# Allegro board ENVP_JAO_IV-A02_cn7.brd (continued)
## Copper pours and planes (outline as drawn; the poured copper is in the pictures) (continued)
VDD_1V2 on L4-VCC1: 129.01,41.27 135.66,41.27 136.47,40.46 136.55,40.41 136.65,40.39 146.2,40.39 147.07,39.52 147.07,32.11 146.71,31.75 145.54,31.75 145.44,31.73 145.36,31.68 145.18,31.5 137.41,31.5 137.32,31.48 137.23,31.42 136.47,30.66 136.42,30.58 136.4,30.48 136.4,27.03 136.04,26.67 128.12,26.67 127.76,27.03 127.76,40.03
VDD_1V8 on TOP: 87.63,77.22 87.88,77.47 90.17,77.47 90.42,77.22 90.42,73.09 90.17,72.83 87.82,72.83 87.63,73.03
VDD_1V8 on TOP: 42.93,71.37 41.91,71.37 41.66,71.12 41.66,69.09 41.78,68.96 43.43,68.96 43.56,69.09 43.56,69.72 43.18,70.1 43.18,71.12
VDD_1V8 on L3-IN1: 35.94,86.49 35.94,69.22 36.2,68.96 43.56,68.96 43.81,69.22 43.81,86.36 43.31,86.87 36.32,86.87
VDD_1V8 on L5-VCC2: outline of 230 points within 12.7,16 186.31,102.87 ; 4 cut-outs
VDD_1V8 on L6-IN2: 35.81,86.87 41.66,86.87 42.67,85.85 42.67,77.47 42.42,77.22 37.34,77.22 35.56,78.99 35.56,86.61
VDD_1V8_DISCHARGE on TOP: 90.93,73.15 92.96,73.15 93.22,73.41 93.22,78.49 92.96,78.74 90.93,78.74 90.68,78.49 90.68,73.41
VDD_3V3 on TOP: 15.24,66.17 13.59,66.17 13.46,66.04 13.46,62.87 14.1,62.87 14.1,63.37 14.22,63.5 15.24,63.5 15.37,63.63 15.37,66.04
VDD_3V3 on BOTTOM: 38.48,93.73 40.89,93.73 41.15,93.47 41.15,87.88 40.89,87.63 35.69,87.63 35.43,87.88 35.43,89.66 35.69,89.92 37.85,89.92 38.23,90.3 38.23,93.47
VDD_3V3 on L4-VCC1: outline of 148 points within 72.39,30.23 182.37,138.43
VDD_3V3 on L5-VCC2: outline of 105 points within 35.43,70.36 166.37,114.05
VDD_3V3 on L5-VCC2: 47.22,38.73 54.63,38.73 54.81,38.56 54.89,38.5 54.99,38.48 60.73,38.48 64.84,34.36 64.93,34.31 65.02,34.29 76.6,34.29 76.96,33.93 76.96,32.51 76.98,32.41 77.04,32.33 77.72,31.64 77.72,30.46 77.49,30.23 67.18,30.23 67.09,30.21 67,30.15 66.44,29.59 46.46,29.59 45.97,30.08 45.97,37.49
VDD_3V3_DISCHARGE on BOTTOM (solid shape): 44.45,90.42 44.45,87.88 44.2,87.63 41.91,87.63 41.66,87.88 41.66,91.19 41.91,91.44 43.43,91.44
VDD_3V3_PD on TOP (solid shape): 49.02,108.2 50.04,108.2 50.29,107.95 50.29,102.87 50.04,102.62 48.01,102.62 47.75,102.87 47.75,107.82 47.62,107.95 47.62,108.33 48.9,108.33
VDD_3V3_PD on BOTTOM (solid shape): 49.53,107.95 49.53,102.87 49.28,102.62 48.01,102.62 47.75,102.87 47.75,107.95 48.01,108.2 49.28,108.2
VDD_3V3_PD on BOTTOM: 49.78,89.41 58.42,89.41 61.47,86.36 61.47,71.88 58.42,68.83 50.04,68.83 49.53,69.34 49.53,71.12 49.78,71.37 53.59,71.37 53.85,71.63 53.85,72.64 54.1,72.9 55.75,72.9 58.17,75.31 58.17,78.23 58.93,78.99 58.93,86.61 57.91,87.63 53.85,87.63 53.09,88.39 49.78,88.39 49.53,88.65 49.53,89.15
VDD_3V3_PD on L3-IN1: 46.48,77.47 46.48,72.64 48.01,71.12 53.09,71.12 53.34,70.87 53.34,69.34 53.09,69.09 44.45,69.09 44.2,69.34 44.2,78.74 44.45,78.99 44.96,78.99
VDD_3V3_PD on L4-VCC1: 44.81,111 60.35,111 65.28,106.07 65.28,82.15 64.92,81.79 63.75,81.79 63.66,81.77 63.57,81.71 61.36,79.5 59.29,79.5 57.84,80.95 57.76,81.01 57.66,81.03 48.37,81.03 46.99,82.4 46.99,86 51.67,90.68 58.17,90.68 58.26,90.7 58.35,90.75 58.98,91.39 59.04,91.47 59.05,91.57 59.05,106.17 59.04,106.27 58.98,106.35 58.47,106.86 58.39,106.91 58.29,106.93 51.31,106.93 51.21,106.91 51.13,106.86 50.11,105.84 50.06,105.76 50.04,105.66 50.04,103.48 49.42,102.87 43.79,102.87 43.43,103.23 43.43,106.98 44.3,107.84 44.41,108.01 44.45,108.2 44.45,110.64
VDD_3V3_PD on L6-IN2: 40.64,108.2 49.53,108.2 49.78,107.95 49.78,92.46 52.32,89.92 56.39,89.92 61.34,84.96 61.34,79.88 61.21,79.76 53.59,79.76 51.31,82.04 50.29,82.04 50.04,81.79 47.5,81.79 40.39,88.9 40.39,107.95
VDD_5V on TOP (solid shape): 52.07,64.52 52.07,57.91 51.82,57.66 41.91,57.66 41.66,57.91 41.66,59.69 41.4,59.94 41.4,64.52 41.66,64.77 51.82,64.77
VDD_5V on TOP (solid shape): 89.41,58.17 89.41,56.13 88.65,55.37 88.65,54.61 87.25,53.21 87.25,51.82 87.12,51.69 87,51.69 86.87,51.82 86.87,52.32 86.74,52.45 86.36,52.45 86.23,52.58 86.23,53.47 85.85,53.85 85.85,58.17 86.11,58.42 89.15,58.42
VDD_5V on BOTTOM (solid shape): 52.07,64.52 52.07,57.91 51.82,57.66 41.66,57.66 41.4,57.91 41.4,64.52 41.66,64.77 51.82,64.77
VDD_5V on TOP: 34.29,66.17 34.42,66.04 36.07,66.04 36.53,66.5 40.46,66.5 40.89,66.93 40.89,68.33 40.77,68.45 36.07,68.45 35.94,68.33 35.94,67.69 35.69,67.44 34.54,67.44 34.29,67.18
VDD_5V on TOP: 85.09,105.66 85.85,106.43 86.36,106.43 86.49,106.55 86.49,107.57 86.61,107.7 86.87,107.7 86.87,106.68 87.5,106.05 87.5,100.2 87.38,100.08 83.82,100.08 83.69,100.2 83.69,103.12 83.82,103.25 84.84,103.25 85.09,103.5
VDD_5V on TOP: 31.62,84.84 31.62,82.3 31.75,82.17 33.15,82.17 34.8,80.52 34.8,77.09 35.18,76.71 39.62,76.71 39.88,76.96 39.88,84.84 39.5,85.22 32,85.22
VDD_5V on BOTTOM: 85.09,106.17 85.34,106.43 86.87,106.43 87.12,106.17 87.12,101.85 85.34,100.08 83.82,100.08 83.69,100.2 83.69,103.12 83.82,103.25 84.84,103.25 85.09,103.5
VDD_5V on BOTTOM: 86.11,58.42 85.85,58.17 85.85,52.58 86.11,52.32 89.03,52.32 89.28,52.58 89.28,58.23 89.09,58.42
VDD_5V on BOTTOM: 182.88,29.46 181.61,29.46 181.48,29.34 181.48,28.07 181.61,27.94 182.88,27.94 183.01,28.07 183.01,29.34
VDD_5V on L4-VCC1: outline of 397 points within 7.62,1.02 187.71,110.87 ; 1 cut-out
VDD_12V on TOP (solid shape): 84.71,135.51 84.71,132.97 84.58,132.84 80.52,132.84 80.39,132.97 80.39,135.51 80.52,135.64 84.58,135.64
VDD_12V on BOTTOM (solid shape): 84.71,135.51 84.71,132.97 84.58,132.84 81.53,132.84 81.28,133.1 81.28,135.38 81.53,135.64 84.58,135.64
VDD_12V on L5-VCC2: 76.45,138.07 76.84,138.46 181.5,138.43 181.61,138.32 181.61,124.57 181.25,124.21 166.73,124.21 164.26,126.67 164.18,126.73 164.08,126.75 85.45,126.75 84.51,127.69 84.43,127.74 84.33,127.76 76.81,127.76 76.45,128.12
VDD_12V_DISCHARGE on TOP (solid shape): 80.01,135.51 80.01,132.97 79.88,132.84 76.83,132.84 76.58,133.1 76.58,135.38 76.83,135.64 79.88,135.64
VDD_AV1V1_HUB on L4-VCC1: 78.59,48.01 92.86,48.01 93.22,47.65 93.22,41.76 89.3,37.85 79.76,37.85 78.99,38.61 77.85,38.61 77.6,38.35 77.6,37.97 78.23,37.34 78.23,36.94 76.09,34.8 74.02,34.8 73.66,35.16 73.66,36.07 73.64,36.17 73.59,36.25 73.08,36.76 73,36.81 72.9,36.83 67.69,36.83 67.59,36.81 67.51,36.76 67.26,36.5 67.2,36.42 67.18,36.32 67.18,35.81 67.2,35.72 67.26,35.63 67.69,35.2 67.69,35.03 67.59,34.92 66.53,34.92 64.26,37.19 64.26,39.01 67.24,41.98 67.29,42.07 67.31,42.16 67.31,43.07 69.19,44.96 73.53,44.96 73.63,44.98 73.71,45.03 75.04,46.35 76.83,46.35 76.93,46.37 77.01,46.43
VDDD_IN_CCG4 on TOP (solid shape): 44.45,108.97 44.45,108.58 44.7,108.33 45.47,108.33 45.47,107.95 45.21,107.7 45.21,101.35 44.96,101.09 41.66,101.09 41.4,101.35 41.4,108.97 41.66,109.22 44.2,109.22
VDDD_IN_CCG4 on BOTTOM: 41.4,102.87 41.4,107.19 41.66,107.44 44.2,107.44 44.45,107.19 44.45,102.87 44.2,102.62 41.66,102.62
CAM_2V8_SW on TOP: 85.09,110.49 84.58,111 84.58,111.76 84.84,112.01 85.6,112.01 85.85,111.76 85.85,111.51 86.11,111.25 88.14,111.25 88.39,111 88.39,108.97 88.14,108.71 87.63,108.71 87.5,108.58 87.5,107.31 87.38,107.19 87.25,107.19 87.12,107.31 87.12,108.97 86.61,109.47 85.34,109.47 85.09,109.73
DI_GND on TOP: 14.73,17.78 10.54,17.78 10.41,17.65 10.41,11.3 10.54,11.18 14.61,11.18 14.86,11.43 14.86,17.65
DI_GND on TOP: 12.06,22.48 9.4,22.48 9.27,22.35 9.27,21.21 9.4,21.08 10.03,21.08 10.41,20.7 10.41,19.94 10.54,19.81 12.06,19.81 12.19,19.94 12.19,22.35
DI_GND on L2-GND1, L4-VCC1, L5-VCC2, L7-GND2: 12.19,29.59 13.21,29.59 13.34,29.46 13.34,29.08 13.46,28.96 24.38,28.96 24.64,28.7 24.64,27.18 24.72,26.79 24.94,26.46 25.7,25.7 26.03,25.48 26.42,25.4 40.98,25.4 42.93,23.46 42.93,5.25 42.76,5.08 14.64,5.08 5.59,14.14 5.59,23.46 5.75,23.62 9.29,23.62 9.73,23.19 9.81,23.13 9.91,23.11 20.83,23.11 20.93,23.13 21.01,23.19 21.52,23.7 21.57,23.78 21.59,23.88 21.59,26.42 21.57,26.51 21.52,26.6 21.01,27.1 20.93,27.16 20.83,27.18 11.28,27.18 10.92,27.54 10.92,28.7 11.18,28.96 11.94,28.96 12.06,29.08 12.06,29.46
DO1_OUT on TOP: 10.92,19.3 10.92,18.41 11.05,18.29 12.95,18.29 13.08,18.41 13.08,19.3 12.95,19.43 11.05,19.43
DO1_OUT on BOTTOM: 12.62,23.04 10.34,23.04 10.24,22.94 10.24,18.44 10.39,18.29 13.13,18.29 13.21,18.36 13.21,20.12 12.59,20.74 12.59,21.4 12.67,21.49 12.67,22.99
DO2_OUT on TOP: 13.21,21.08 13.21,18.41 13.34,18.29 14.73,18.29 14.86,18.41 14.86,21.08 14.73,21.21 13.34,21.21
DO2_OUT on BOTTOM: 12.88,23.04 12.83,22.99 12.83,20.93 13.49,20.27 13.49,18.36 13.56,18.29 15.62,18.29 15.75,18.41 15.75,20.32 15.62,20.45 14.99,20.45 13.97,21.46 13.97,22.99 13.92,23.04
DO2_OUT on L3-IN1: 9.02,13.46 16.51,5.97 23.5,5.97 23.75,6.22 23.75,8.76 23.5,9.02 17.53,9.02 11.94,14.61 11.94,19.68 12.45,20.19 14.22,20.19 14.35,20.32 14.35,22.1 14.22,22.23 9.4,22.23 9.02,21.84
DO_GND1 on TOP: 12.06,46.48 12.06,45.72 12.19,45.59 13.46,45.59 13.59,45.72 13.59,46.48 13.46,46.61 12.19,46.61
DO_GND1 on BOTTOM: 12.19,45.59 13.46,45.59 13.59,45.72 13.59,46.48 13.46,46.61 12.19,46.61 12.06,46.48 12.06,45.72
DO_VIO on BOTTOM: 13.34,45.34 12.19,45.34 12.06,45.21 12.06,42.04 12.19,41.91 12.95,41.91 13.08,42.04 13.08,44.2 13.59,44.7 13.59,45.09
GB_AVDDL on L4-VCC1: 145.65,31.24 148.23,31.24 148.59,30.88 148.59,27.03 148.23,26.67 137.27,26.67 136.91,27.03 136.91,30.37 137.52,30.99 145.29,30.99 145.39,31.01 145.47,31.06
GB_VDDIO on L5-VCC2: 128.63,41.4 135.53,41.4 136.47,40.46 136.55,40.41 136.65,40.39 147.72,40.39 150.11,37.99 150.11,35.16 149.17,34.22 149.12,34.13 149.1,34.04 149.1,24.89 149.12,24.79 149.17,24.71 150.19,23.7 150.27,23.64 150.37,23.62 153.82,23.62 154.43,23.01 154.43,18.9 154.07,18.54 144.38,18.54 144.02,18.9 144.02,20.83 144,20.93 143.94,21.01 143.44,21.52 143.35,21.57 143.26,21.59 139.19,21.59 139.09,21.57 139.01,21.52 138.5,21.01 138.45,20.93 138.43,20.83 138.43,18.9 138.07,18.54 123.8,18.54 123.44,18.9 123.44,21.48 127.69,25.73 127.74,25.81 127.76,25.91 127.76,40.53
HDMI_GND on L2-GND1: outline of 92 points within 117.6,1.02 160.27,21.84
HDMI_GND on L2-GND1: outline of 113 points within 1.02,1.02 103.12,100.97
HDMI_GND on L4-VCC1: outline of 200 points within 1.02,1.02 160.27,100.97
HDMI_GND on L5-VCC2: outline of 206 points within 1.02,1.02 160.27,100.97
HDMI_GND on L7-GND2: outline of 197 points within 1.02,1.02 160.27,100.97
ISO1_5V on TOP: 8.89,11.18 10.03,11.18 10.16,11.3 10.16,14.73 10.03,14.86 8.51,14.86 8.38,14.73 8.38,12.83 8.76,12.45 8.76,11.3
M2B_3V3 on L5-VCC2: 158.6,82.04 165.5,82.04 165.86,81.68 165.86,73.66 165.88,73.56 165.94,73.48 166.37,73.05 166.37,57 166.01,56.64 158.6,56.64 158.24,57 158.24,81.68
M2E_3V3 on L5-VCC2: 145.9,78.49 148.23,78.49 148.59,78.13 148.59,75.44 148.61,75.34 148.66,75.26 150.11,73.81 150.11,59.03 149.75,58.67 146.28,58.67 145.8,59.16 145.8,69.34 145.78,69.44 145.72,69.52 144.53,70.72 144.53,75.59 145.09,76.15 145.14,76.23 145.16,76.33 145.16,77.75
M2M_3V3 on L5-VCC2: 157.59,105.92 162.58,105.92 162.81,105.69 162.81,103.18 162.81,103.12 162.81,102.41 162.81,102.35 162.81,91.95 162.83,91.85 162.89,91.77 163.32,91.33 163.32,87.48 161.95,86.11 158.32,86.11 157.73,86.7 157.73,98.04 157.71,98.14 157.66,98.22 157.23,98.66 157.23,105.56
M_USB_GND on L2-GND1, L4-VCC1: 182.78,138.98 188,138.98 188.69,138.7 188.98,138 188.98,114.04 189.36,114.04 189.36,113.16 188.98,113.16 188.98,105.03 189.36,105.03 189.36,104.14 188.98,104.14 188.98,87.36 188.49,86.87 187.3,86.87 186.82,87.35 186.82,101.98 186.8,102.08 186.74,102.16 185.6,103.3 185.52,103.36 185.42,103.38 182.48,103.38 182.12,103.74 182.12,104.54 182.73,105.16 183.79,105.16 184.22,104.72 184.31,104.67 184.4,104.65 185.42,104.65 185.52,104.67 185.6,104.72 186.11,105.23 186.16,105.31 186.18,105.41 186.18,113.28 186.16,113.38 186.11,113.46 185.47,114.1 185.39,114.15 185.29,114.17 184.53,114.17 184.43,114.15 184.35,114.1 183.28,113.03 182.48,113.03 182.12,113.39 182.12,117.24 182.48,117.6 186.44,117.6 186.53,117.62 186.62,117.68 187.12,118.18 187.18,118.27 187.2,118.36 187.2,127.76 187.18,127.86 187.12,127.94 182.12,132.95 182.12,138.32
M_USB_GND on L5-VCC2, L7-GND2: 182.78,138.98 188,138.98 188.69,138.7 188.98,138 188.98,114.04 189.36,114.04 189.36,113.16 188.98,113.16 188.98,105.03 189.36,105.03 189.36,104.14 188.98,104.14 188.98,87.36 188.49,86.87 187.3,86.87 186.82,87.35 186.82,101.98 186.8,102.08 186.74,102.16 185.6,103.3 185.52,103.36 185.42,103.38 182.48,103.38 182.12,103.74 182.12,104.54 182.73,105.16 183.79,105.16 184.22,104.72 184.31,104.67 184.4,104.65 185.42,104.65 185.52,104.67 185.6,104.72 186.11,105.23 186.16,105.31 186.18,105.41 186.18,113.03 186.16,113.13 186.11,113.21 185.85,113.46 185.77,113.52 185.67,113.54 184.91,113.54 184.81,113.52 184.73,113.46 184.3,113.03 182.48,113.03 182.12,113.39 182.12,117.24 182.48,117.6 186.44,117.6 186.53,117.62 186.62,117.68 187.12,118.18 187.18,118.27 187.2,118.36 187.2,127.76 187.18,127.86 187.12,127.94 182.12,132.95 182.12,138.32
MGBE_0V7 on L5-VCC2: 111.61,38.35 113.69,38.35 114.55,37.49 114.55,33.25 114.19,32.89 105.64,32.89 105.16,33.38 105.16,37.23 105.52,37.59 110.74,37.59 110.84,37.61 110.92,37.67
MGBE_VDDIO on L5-VCC2: 104.5,40.89 120.29,40.89 120.72,40.46 120.81,40.41 120.9,40.39 126.89,40.39 127.25,40.03 127.25,26.01 123.08,21.84 120.14,21.84 120.04,21.82 119.96,21.77 119.27,21.08 103.99,21.08 103.63,21.44 103.63,22.1 103.61,22.2 103.56,22.28 98.04,27.79 98.04,37.23 101.45,40.64 104.14,40.64 104.24,40.66 104.32,40.71 ; 1 cut-out
MIC2128_3V3_SW on TOP (solid shape): 67.06,100.84 67.06,96.52 66.8,96.52 66.29,97.03 65.28,97.03 64.26,96.01 59.18,96.01 58.93,95.76 58.93,92.46 59.56,91.82 59.56,90.68 60.26,89.98 60.26,89.41 60.13,89.28 59.82,89.28 58.71,90.39 54.39,90.39 53.85,90.93 53.85,100.84 54.1,101.09 66.8,101.09
PCIE_3V3 on L4-VCC1: 162.67,138.43 181.5,138.43 181.61,138.32 181.61,132.84 181.63,132.74 181.68,132.66 186.69,127.66 186.69,124.06 186.33,123.7 182.48,123.7 182.04,124.13 181.96,124.19 181.86,124.21 164.19,124.21 162.31,126.09 162.31,138.07
PS_1V8_SW on TOP: 80.01,82.17 80.01,82.3 80.14,82.42 81.92,82.42 82.42,82.93 82.42,84.45 82.55,84.58 86.87,84.58 87.12,84.33 87.12,81.53 86.87,81.28 82.3,81.28 81.53,82.04 80.14,82.04
PS_12_CS on TOP (solid shape): 73.15,127.76 73.15,123.95 72.9,123.7 71.88,123.7 71.37,124.21 70.36,124.21 70.1,123.95 70.1,123.44 69.6,122.94 68.58,122.94 68.33,123.19 68.33,126.49 68.58,126.75 69.34,126.75 69.85,126.24 70.87,126.24 71.12,126.49 71.12,127.76 71.37,128.02 72.9,128.02
PS_12_CS on BOTTOM (solid shape): 73.15,127.76 73.15,124.97 72.9,124.71 70.87,124.71 70.1,123.95 70.1,123.7 69.6,123.19 68.83,123.19 68.58,123.44 68.58,127.25 68.83,127.51 70.87,127.51 71.37,128.02 72.9,128.02
PS_12V_OUT on TOP: 76.71,132.08 76.96,132.33 81.53,132.33 81.79,132.08 81.79,123.95 82.04,123.7 81.66,123.7 81.28,123.32 81.28,121.16 79.88,119.76 77.85,119.76 77.6,120.02 77.6,122.17 77.72,122.3 78.99,122.3 79.25,122.05 80.01,122.05 80.39,122.43 80.39,123.44 80.14,123.7 77.98,123.7 77.72,123.44 77.72,123.06 77.6,122.94 76.83,122.94 76.71,123.06
PS_12V_OUT on BOTTOM: 76.71,132.08 76.96,132.33 84.58,132.33 84.71,132.21 84.71,128.02 84.58,127.89 82.17,127.89 81.79,127.51 81.79,123.95 81.53,123.7 76.96,123.7 76.71,123.95
PS_12V_OUT on L4-VCC1: 76.81,132.33 83.97,132.33 84.33,131.97 84.33,123.8 83.71,123.19 76.81,123.19 76.45,123.55 76.45,131.97
PS_12V_SW1 on TOP (solid shape): 67.56,137.41 67.56,122.94 68.07,122.43 68.45,122.43 68.58,122.3 68.58,119.89 68.33,119.89 65.28,122.94 65.28,127.76 64.52,128.52 60.2,128.52 59.94,128.78 59.94,137.41 60.2,137.67 67.31,137.67
PS_12V_SW2 on TOP (solid shape): 76.2,137.41 76.2,123.19 75.69,122.68 74.68,122.68 74.42,122.43 74.42,120.4 73.15,120.4 72.9,120.65 72.9,122.17 73.66,122.94 73.66,128.02 72.9,128.78 69.34,128.78 69.09,129.03 69.09,137.41 69.34,137.67 75.95,137.67
PS_20_CS on TOP (solid shape): 38.1,121.16 38.1,117.6 37.85,117.35 37.08,117.35 36.58,116.84 32,116.84 31.24,116.08 31.24,114.05 30.99,113.79 30.48,113.79 30.23,114.05 30.23,119.38 30.48,119.63 33.53,119.63 33.78,119.89 33.78,121.16 34.04,121.41 37.85,121.41
PS_20_CS on BOTTOM (solid shape): 38.35,121.16 38.35,117.35 38.1,117.09 30.99,117.09 30.73,117.35 30.73,119.89 30.99,120.14 33.53,120.14 33.78,120.4 33.78,121.16 34.04,121.41 38.1,121.41
PS_20V_SW1 on TOP (solid shape): 29.46,138.43 29.46,116.08 29.21,115.82 27.18,115.82 26.92,115.57 26.92,114.3 24.89,112.27 24.89,129.54 24.64,129.79 21.34,129.79 21.08,130.05 21.08,138.43 21.59,138.94 28.96,138.94
PS_20V_SW2 on TOP (solid shape): 44.45,135.64 47.75,135.64 48.01,135.38 48.01,127.25 47.75,127 44.2,127 43.69,126.49 43.69,116.33 43.43,116.08 40.13,116.08 39.62,115.57 39.62,113.79 39.37,114.05 38.35,114.05 38.1,114.3 38.1,115.82 38.86,116.59 38.86,136.4 39.12,136.65 43.43,136.65
SP339_5V on TOP: 32.89,81.79 30.1,81.79 29.84,81.53 29.84,75.31 30.1,75.06 31.24,75.06 31.5,75.31 31.5,77.72 33.27,79.5 33.27,81.41
SP339_5V on L3-IN1: 33.53,98.55 22.61,98.55 22.1,98.04 22.1,73.15 22.61,72.64 26.42,72.64 27.43,73.66 31.88,73.66 34.04,75.82 34.04,98.04
USBC1_VBUS on TOP (solid shape): 41.15,102.62 41.15,100.84 40.89,100.58 38.86,100.58 38.61,100.84 38.61,102.62 38.86,102.87 40.89,102.87
USBC1_VBUS on BOTTOM (solid shape): 41.15,102.62 41.15,100.84 40.89,100.58 38.86,100.58 38.61,100.84 38.61,102.62 38.86,102.87 40.89,102.87
USBC1_VBUS on TOP: 29.46,69.72 26.8,69.72 26.67,69.6 26.67,66.67 26.8,66.55 29.46,66.55 29.84,66.17 31.88,66.17 32,66.04 33.91,66.04 34.04,66.17 34.04,67.31 34.42,67.69 35.56,67.69 35.69,67.82 35.69,68.96 35.56,69.09 30.1,69.09
USBC1_VBUS on L5-VCC2: 179.81,113.79 181.25,113.79 181.61,113.43 181.61,113.28 181.63,113.19 181.68,113.1 182.19,112.6 182.27,112.54 182.37,112.52 184.4,112.52 184.5,112.54 184.58,112.6 184.66,112.67 184.66,109.86 184.4,109.6 184.4,108.46 184.66,108.2 184.66,106.81 184.02,106.17 184.02,105.63 183.96,105.66 183.9,105.66 182.63,105.66 182.53,105.64 182.45,105.59 181.68,104.83 181.63,104.75 181.61,104.65 181.61,103.74 181.25,103.38 178.92,103.38 178.56,103.74 178.56,112.54
USBC1_VBUS on L5-VCC2: outline of 136 points within 21.59,66.29 181.61,127.25
N7372642 on TOP: 83.82,80.77 86.87,80.77 87.12,80.52 87.12,75.69 86.87,75.44 82.8,75.44 82.55,75.69 82.55,79.25 82.8,79.5 83.31,79.5 83.57,79.76 83.57,80.52
N7372642 on BOTTOM: 84.2,79.5 82.8,79.5 82.55,79.25 82.55,76.96 82.8,76.71 84.2,76.71 84.45,76.96 84.45,79.25
N7382555 on TOP (solid shape): 80.14,68.33 80.14,65.53 80.64,65.02 82.93,65.02 83.19,64.77 83.19,61.98 82.93,61.72 76.07,61.72 75.82,61.98 75.82,68.33 76.07,68.58 79.88,68.58
N7440074 on TOP (solid shape): 64.26,107.95 64.26,107.19 64.01,106.93 63.25,106.93 62.99,106.68 62.99,105.16 62.74,104.9 61.47,104.9 61.21,105.16 61.21,107.95 61.47,108.2 64.01,108.2
N7899622 on TOP: 37.08,70.87 30.35,70.87 30.23,70.74 30.23,69.6 30.35,69.47 35.81,69.47 36.2,69.09 37.08,69.09 37.21,69.22 37.21,70.74
N8148459 on TOP: 89.15,110.74 93.22,110.74 93.34,110.87 93.34,112.01 93.09,112.27 89.92,112.27 89.15,113.03 86.36,113.03 86.11,112.78 86.11,111.76 86.36,111.51 88.39,111.51

Small or netless copper shapes (teardrops, artwork), in the pictures only: 11 on TOP

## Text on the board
Ref Des/Silkscreen Top: C | A | P/N : 4190FSG1002 | eNVP-JAO-IV | REV :A0.2_0_0 | MADE IN TAIWAN
USER_PART_NUM_BOTTOM: AG3700
TOLERANCE_BOTTOM: ?4.00 | 5.00 | 15.00 | 3 | 2 | 1 | 22 | 15 | 8 | 9 | 4 | 11 | 12 | 10 | 6 | 20 | 5 | 21 | 30 | 40 | 31 | 23 | 88 | 7 | 16 | 13 | 44 | 67 | B82 | A82 | 18 | H | G | F | E | D | C | B | A | R10 | R9 | L3 | L4 | product profile | PCB EDGE | L2 | L1 | R2 | R1 | 74 | 75 | B12 | A12 | B11 | A11 | PCB ROUTE | 48 | B1 | A1 | 37 | 24 | 20.00 | 10.00 | 119 | 120 | 62 | 61 | 59 | 60 | C3 | C2 | C6 | C5 | C7 | C1 | CD | TRAYECT | 28 | 14 | 66 | 45 | 36 | 25
User.29: DRILL_L1-L2
User.30: DRILL_L2-L3
User.31: DRILL_L3-L6
User.32: DRILL_L6-L7
User.33: DRILL_L7-L8
User.34: LAYER | NO: | VCC1 PLANE
User.36: FIGURE | FINISHED_SIZE | 8.0 | 10.0 | 12.0 | 16.0 | 20.0 | 22.0 | 24.0 | 28.0 | 32.0 | 35.0 | 36.0 | 40.0 | 43.0 | 50.0 | 52.0 | 55.0 | 60.0 | 62.0 | 63.0 | 71.0 | 91.0 | 126.0 | 136.0 | 138.0 | 150.0 | 26.0 | 44.0 | 48.0 | 67.0 | 128.0 | 157.0 | 28.0x20.0 | 36.0x16.0 | 44.0x20.0 | 52.0x20.0 | 60.0x24.0 | 107.0x36.0 | 38.0x26.0 | DRILL CHART: TOP to BOTTOM | ALL UNITS ARE IN MILS | ROTATION | - | 90.000 | 0.000 | PLATED | NON-PLATED | QTY | 3 | 118 | 4231 | 10 | 4 | 19 | 12 | 36 | 66 | 18 | 8 | 6 | 2 | 1 | 7
User.37: FIGURE | FINISHED_SIZE | 4.0 | DRILL CHART: TOP to L2-GND1 | ALL UNITS ARE IN MILS | ROTATION | - | PLATED | QTY | 261
User.38: FIGURE | FINISHED_SIZE | 4.0 | DRILL CHART: L2-GND1 to L3-IN1 | ALL UNITS ARE IN MILS | ROTATION | - | PLATED | QTY | 228
User.39: FIGURE | FINISHED_SIZE | 8.0 | DRILL CHART: L3-IN1 to L6-IN2 | ALL UNITS ARE IN MILS | ROTATION | - | PLATED | QTY | 191
User.40: FIGURE | FINISHED_SIZE | 4.0 | DRILL CHART: L6-IN2 to L7-GND2 | ALL UNITS ARE IN MILS | ROTATION | - | PLATED | QTY | 473
User.41: FIGURE | FINISHED_SIZE | 4.0 | DRILL CHART: L7-GND2 to BOTTOM | ALL UNITS ARE IN MILS | ROTATION | - | PLATED | QTY | 630
